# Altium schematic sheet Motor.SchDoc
size A2
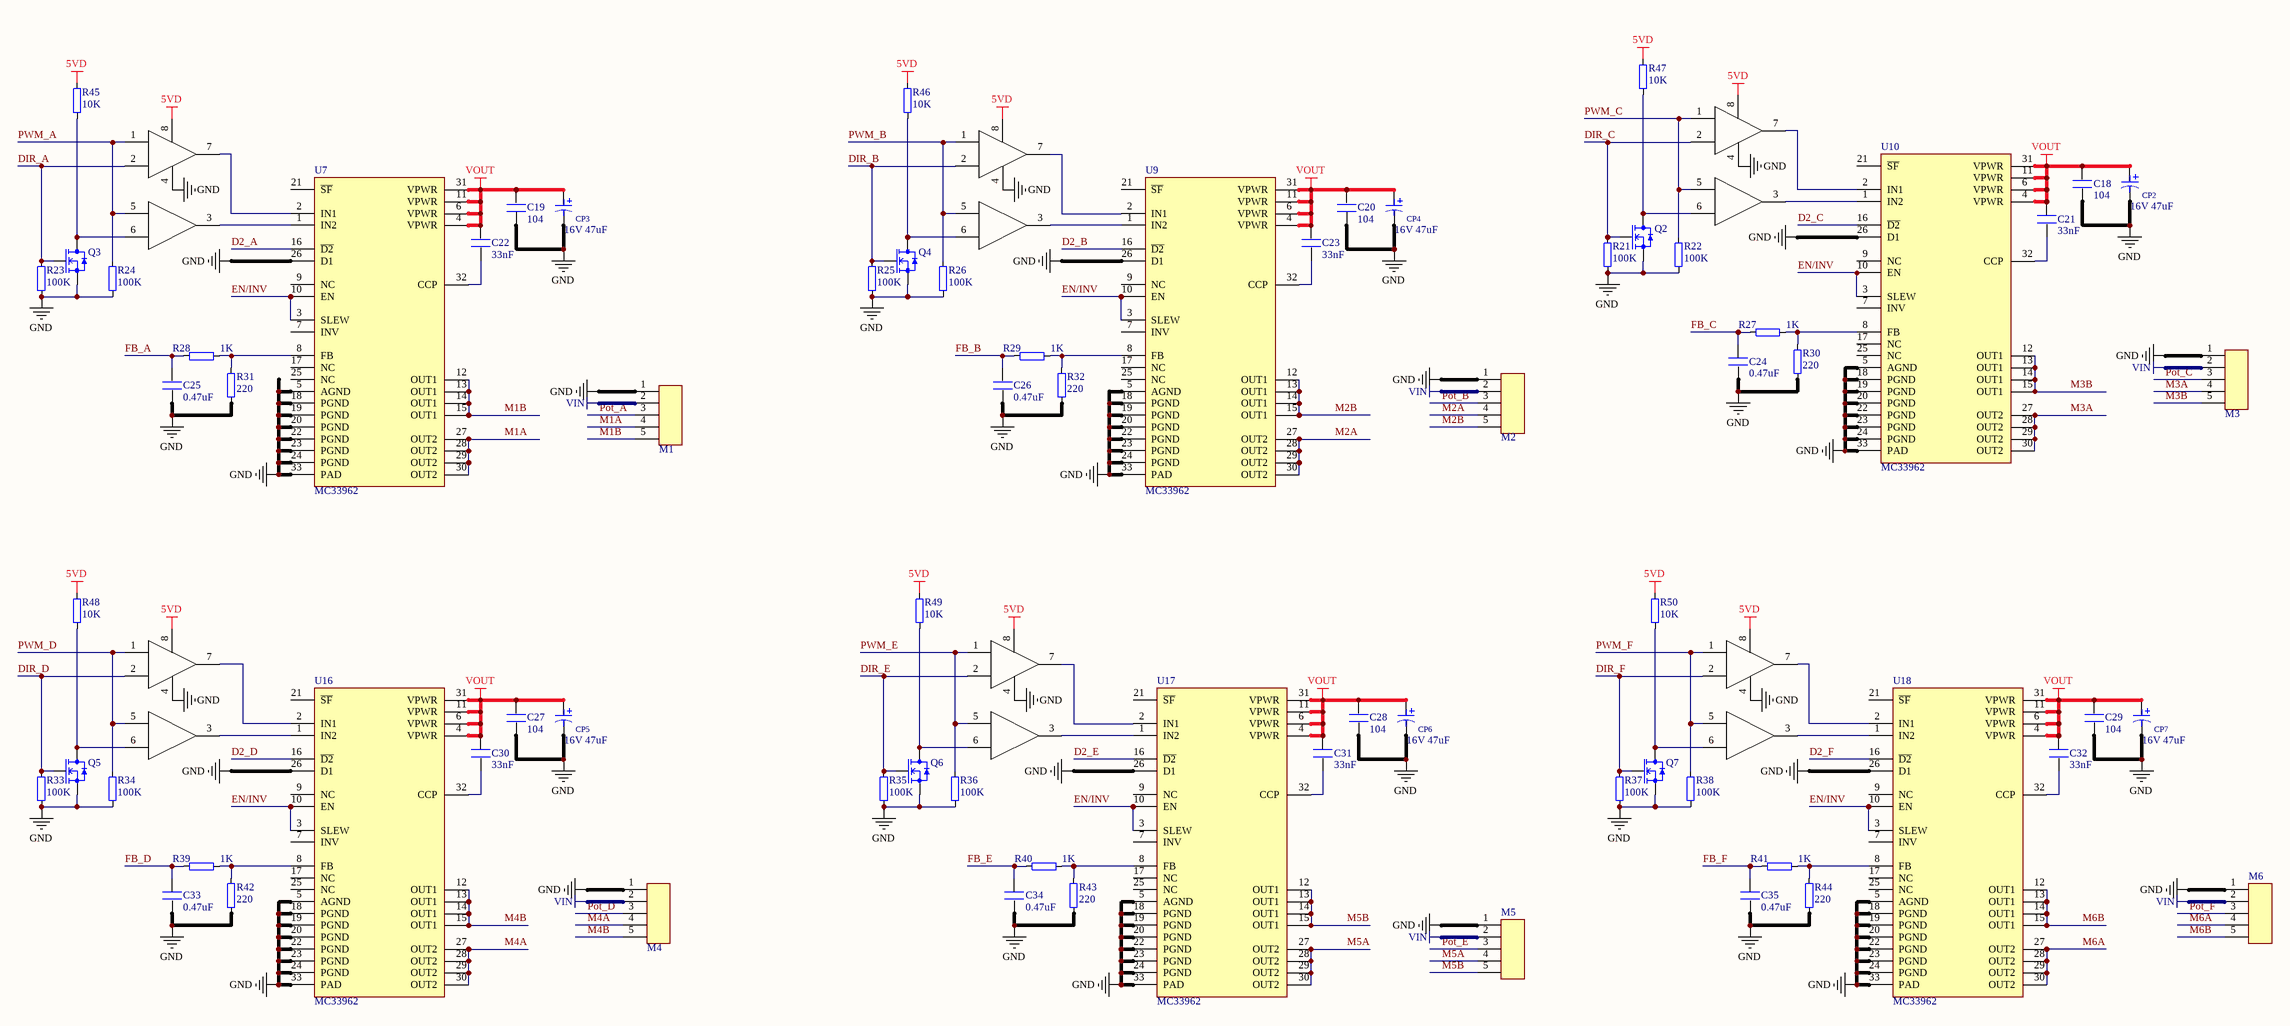
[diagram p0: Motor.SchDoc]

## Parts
C18  104  [SM0603C]
C19  104  [SM0603C]
C20  104  [SM0603C]
C21  33nF  [SM0603C]
C22  33nF  [SM0603C]
C23  33nF  [SM0603C]
C24  0.47uF  [SM0603C]
C25  0.47uF  [SM0603C]
C26  0.47uF  [SM0603C]
C27  104  [SM0603C]
C28  104  [SM0603C]
C29  104  [SM0603C]
C30  33nF  [SM0603C]
C31  33nF  [SM0603C]
C32  33nF  [SM0603C]
C33  0.47uF  [SM0603C]
C34  0.47uF  [SM0603C]
C35  0.47uF  [SM0603C]
CP2  16V 47uF  [SMD5-Al]
CP3  16V 47uF  [SMD5-Al]
CP4  16V 47uF  [SMD5-Al]
CP5  16V 47uF  [SMD5-Al]
CP6  16V 47uF  [SMD5-Al]
CP7  16V 47uF  [SMD5-Al]
M1  JC5  [FCI_SFW5R-1STE1LF]  (value not drawn)
M2  JC5  [FCI_SFW5R-1STE1LF]  (value not drawn)
M3  JC5  [FCI_SFW5R-1STE1LF]  (value not drawn)
M4  JC5  [FCI_SFW5R-1STE1LF]  (value not drawn)
M5  JC5  [FCI_SFW5R-1STE1LF]  (value not drawn)
M6  JC5  [FCI_SFW5R-1STE1LF]  (value not drawn)
Q2  2N7002  [SOT23-3]  (value not drawn)
Q3  2N7002  [SOT23-3]  (value not drawn)
Q4  2N7002  [SOT23-3]  (value not drawn)
Q5  2N7002  [SOT23-3]  (value not drawn)
Q6  2N7002  [SOT23-3]  (value not drawn)
Q7  2N7002  [SOT23-3]  (value not drawn)
R21  100K  [SM0603R]
R22  100K  [SM0603R]
R23  100K  [SM0603R]
R24  100K  [SM0603R]
R25  100K  [SM0603R]
R26  100K  [SM0603R]
R27  1K  [SM0603R]
R28  1K  [SM0603R]
R29  1K  [SM0603R]
R30  220  [SM0603R]
R31  220  [SM0603R]
R32  220  [SM0603R]
R33  100K  [SM0603R]
R34  100K  [SM0603R]
R35  100K  [SM0603R]
R36  100K  [SM0603R]
R37  100K  [SM0603R]
R38  100K  [SM0603R]
R39  1K  [SM0603R]
R40  1K  [SM0603R]
R41  1K  [SM0603R]
R42  220  [SM0603R]
R43  220  [SM0603R]
R44  220  [SM0603R]
R45  10K  [SM0603R]
R46  10K  [SM0603R]
R47  10K  [SM0603R]
R48  10K  [SM0603R]
R49  10K  [SM0603R]
R50  10K  [SM0603R]
U4  74XXX  [LC-VSSOP-8_2x2.3x05P]  (value not drawn)  (parts A,B of 2)
U5  74XXX  [LC-VSSOP-8_2x2.3x05P]  (value not drawn)  (parts A,B of 2)
U6  74XXX  [LC-VSSOP-8_2x2.3x05P]  (value not drawn)  (parts A,B of 2)
U7  MC33962  [PQFN32_0P8_8X8_SLUG]
U8  74XXX  [LC-VSSOP-8_2x2.3x05P]  (value not drawn)  (parts A,B of 2)
U9  MC33962  [PQFN32_0P8_8X8_SLUG]
U10  MC33962  [PQFN32_0P8_8X8_SLUG]
U11  74XXX  [LC-VSSOP-8_2x2.3x05P]  (value not drawn)  (parts A,B of 2)
U12  74XXX  [LC-VSSOP-8_2x2.3x05P]  (value not drawn)  (parts A,B of 2)
U16  MC33962  [PQFN32_0P8_8X8_SLUG]
U17  MC33962  [PQFN32_0P8_8X8_SLUG]
U18  MC33962  [PQFN32_0P8_8X8_SLUG]

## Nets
5VD: R45.2 R46.2 R47.2 R48.2 R49.2 R50.2 U4.8 U5.8 U6.8 U8.8 U11.8 U12.8
GND: C18.1 C19.1 C20.1 C24.2 C25.2 C26.2 C27.1 C28.1 C29.1 C33.2 C34.2 C35.2 CP2.2 CP3.2 CP4.2 CP5.2 CP6.2 CP7.2 M1.1 M2.1 M3.1 M4.1 M5.1 M6.1 Q2.2(S) Q3.2(S) Q4.2(S) Q5.2(S) Q6.2(S) Q7.2(S) R21.1 R22.1 R23.1 R24.1 R25.1 R26.1 R30.1 R31.1 R32.1 R33.1 R34.1 R35.1 R36.1 R37.1 R38.1 R42.1 R43.1 R44.1 U4.4 U5.4 U6.4 U7.5(AGND) U7.18(PGND) U7.19(PGND) U7.20(PGND) U7.22(PGND) U7.23(PGND) U7.24(PGND) U7.26(D1) U7.33(PAD) U8.4 U9.5(AGND) U9.18(PGND) U9.19(PGND) U9.20(PGND) U9.22(PGND) U9.23(PGND) U9.24(PGND) U9.26(D1) U9.33(PAD) U10.5(AGND) U10.18(PGND) U10.19(PGND) U10.20(PGND) U10.22(PGND) U10.23(PGND) U10.24(PGND) U10.26(D1) U10.33(PAD) U11.4 U12.4 U16.5(AGND) U16.18(PGND) U16.19(PGND) U16.20(PGND) U16.22(PGND) U16.23(PGND) U16.24(PGND) U16.26(D1) U16.33(PAD) U17.5(AGND) U17.18(PGND) U17.19(PGND) U17.20(PGND) U17.22(PGND) U17.23(PGND) U17.24(PGND) U17.26(D1) U17.33(PAD) U18.5(AGND) U18.18(PGND) U18.19(PGND) U18.20(PGND) U18.22(PGND) U18.23(PGND) U18.24(PGND) U18.26(D1) U18.33(PAD)
VIN: M1.2 M2.2 M3.2 M4.2 M5.2 M6.2
VOUT: C18.2 C19.2 C20.2 C21.1 C22.1 C23.1 C27.2 C28.2 C29.2 C30.1 C31.1 C32.1 CP2.1 CP3.1 CP4.1 CP5.1 CP6.1 CP7.1 U7.4(VPWR) U7.6(VPWR) U7.11(VPWR) U7.31(VPWR) U9.4(VPWR) U9.6(VPWR) U9.11(VPWR) U9.31(VPWR) U10.4(VPWR) U10.6(VPWR) U10.11(VPWR) U10.31(VPWR) U16.4(VPWR) U16.6(VPWR) U16.11(VPWR) U16.31(VPWR) U17.4(VPWR) U17.6(VPWR) U17.11(VPWR) U17.31(VPWR) U18.4(VPWR) U18.6(VPWR) U18.11(VPWR) U18.31(VPWR)
D2_A: U7.16(~{D2})
D2_B: U9.16(~{D2})
D2_C: U10.16(~{D2})
D2_D: U16.16(~{D2})
D2_E: U17.16(~{D2})
D2_F: U18.16(~{D2})
DIR_A: Q3.1(G) R23.2 U4.2
DIR_B: Q4.1(G) R25.2 U5.2
DIR_C: Q2.1(G) R21.2 U6.2
DIR_D: Q5.1(G) R33.2 U8.2
DIR_E: Q6.1(G) R35.2 U11.2
DIR_F: Q7.1(G) R37.2 U12.2
EN/INV: U7.3(SLEW) U7.10(EN) U9.3(SLEW) U9.10(EN) U10.3(SLEW) U10.10(EN) U16.3(SLEW) U16.10(EN) U17.3(SLEW) U17.10(EN) U18.3(SLEW) U18.10(EN)
FB_A: C25.1 R28.1
FB_B: C26.1 R29.1
FB_C: C24.1 R27.1
FB_D: C33.1 R39.1
FB_E: C34.1 R40.1
FB_F: C35.1 R41.1
M1A: M1.4 U7.27(OUT2) U7.28(OUT2) U7.29(OUT2) U7.30(OUT2)
M1B: M1.5 U7.12(OUT1) U7.13(OUT1) U7.14(OUT1) U7.15(OUT1)
M2A: M2.4 U9.27(OUT2) U9.28(OUT2) U9.29(OUT2) U9.30(OUT2)
M2B: M2.5 U9.12(OUT1) U9.13(OUT1) U9.14(OUT1) U9.15(OUT1)
M3A: M3.4 U10.27(OUT2) U10.28(OUT2) U10.29(OUT2) U10.30(OUT2)
M3B: M3.5 U10.12(OUT1) U10.13(OUT1) U10.14(OUT1) U10.15(OUT1)
M4A: M4.4 U16.27(OUT2) U16.28(OUT2) U16.29(OUT2) U16.30(OUT2)
M4B: M4.5 U16.12(OUT1) U16.13(OUT1) U16.14(OUT1) U16.15(OUT1)
M5A: M5.4 U17.27(OUT2) U17.28(OUT2) U17.29(OUT2) U17.30(OUT2)
M5B: M5.5 U17.12(OUT1) U17.13(OUT1) U17.14(OUT1) U17.15(OUT1)
M6A: M6.4 U18.27(OUT2) U18.28(OUT2) U18.29(OUT2) U18.30(OUT2)
M6B: M6.5 U18.12(OUT1) U18.13(OUT1) U18.14(OUT1) U18.15(OUT1)
Pot_A: M1.3
Pot_B: M2.3
Pot_C: M3.3
Pot_D: M4.3
Pot_E: M5.3
Pot_F: M6.3
PWM_A: R24.2 U4.1 U4.5
PWM_B: R26.2 U5.1 U5.5
PWM_C: R22.2 U6.1 U6.5
PWM_D: R34.2 U8.1 U8.5
PWM_E: R36.2 U11.1 U11.5
PWM_F: R38.2 U12.1 U12.5
NetC21_2: C21.2 U10.32(CCP)
NetC22_2: C22.2 U7.32(CCP)
NetC23_2: C23.2 U9.32(CCP)
NetC30_2: C30.2 U16.32(CCP)
NetC31_2: C31.2 U17.32(CCP)
NetC32_2: C32.2 U18.32(CCP)
NetQ2_3: Q2.3(D) R47.1 U6.6
NetQ3_3: Q3.3(D) R45.1 U4.6
NetQ4_3: Q4.3(D) R46.1 U5.6
NetQ5_3: Q5.3(D) R48.1 U8.6
NetQ6_3: Q6.3(D) R49.1 U11.6
NetQ7_3: Q7.3(D) R50.1 U12.6
NetR27_2: R27.2 R30.2 U10.8(FB)
NetR28_2: R28.2 R31.2 U7.8(FB)
NetR29_2: R29.2 R32.2 U9.8(FB)
NetR39_2: R39.2 R42.2 U16.8(FB)
NetR40_2: R40.2 R43.2 U17.8(FB)
NetR41_2: R41.2 R44.2 U18.8(FB)
NetU4_3: U4.3 U7.1(IN2)
NetU4_7: U4.7 U7.2(IN1)
NetU5_3: U5.3 U9.1(IN2)
NetU5_7: U5.7 U9.2(IN1)
NetU6_3: U6.3 U10.1(IN2)
NetU6_7: U6.7 U10.2(IN1)
NetU8_3: U8.3 U16.1(IN2)
NetU8_7: U8.7 U16.2(IN1)
NetU11_3: U11.3 U17.1(IN2)
NetU11_7: U11.7 U17.2(IN1)
NetU12_3: U12.3 U18.1(IN2)
NetU12_7: U12.7 U18.2(IN1)

Not connected (* = marked no-connect by the designer): U7 7(INV) 9(NC) 17(NC) 21(~{SF}) 25(NC); U9 7(INV) 9(NC) 17(NC) 21(~{SF}) 25(NC); U10 7(INV) 9(NC) 17(NC) 21(~{SF}) 25(NC); U16 7(INV) 9(NC) 17(NC) 21(~{SF}) 25(NC); U17 7(INV) 9(NC) 17(NC) 21(~{SF}) 25(NC); U18 7(INV) 9(NC) 17(NC) 21(~{SF}) 25(NC)

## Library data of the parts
C18-C35 = C
CP2-CP7 = 2.1.2.50.5162200: Cap, 22uF, 20%, 16V; Manufactory: ALUMINUM; InstallMode: SMD
Q2-Q7 = 2.1.4.40.0270020: Mos/N, 2N7002, 7.5 OHM, 0.5A, SOT23-3, Supertex; Manufactory: Supertex inc.; Name: N-Channel Enhancement-Mode Vertical DMOS FETs; InstallMode: SMD
R21-R50 = RES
